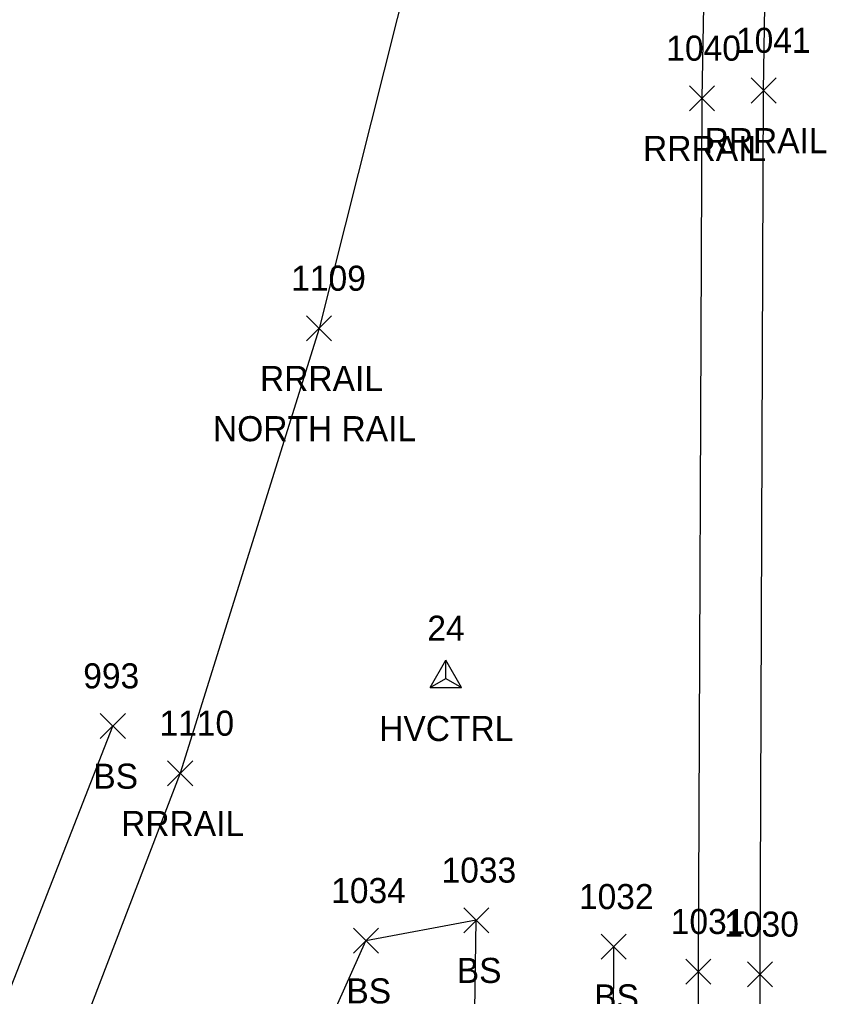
# Model space of a CAD drawing. Extents: x 1764889 to 1767296, y 695936 to 698960.
# Drawn here: x 1766353.9 to 1766418.2, y 696640.9 to 696718.8 of the extents above; entities that cross this region are included whole.
import ezdxf

# ---------------------------------------------------------------- set-up
doc = ezdxf.new("R2010")
doc.units = 0
for name, color, linetype in [('C_A', 7, 'Continuous'), ('C_I', 7, 'Continuous'), ('CPSM', 7, 'Continuous'), ('L_A', 7, 'Continuous'), ('L_I', 7, 'Continuous'), ('L_TIC', 7, 'Continuous'), ('LELB', 7, 'Continuous'), ('R_A', 7, 'Continuous'), ('R_C', 7, 'Continuous'), ('R_I', 7, 'Continuous'), ('R_TIC', 7, 'Continuous'), ('RR', 7, 'Continuous')]:
    doc.layers.add(name, color=color, linetype=linetype)

msp = doc.modelspace()

# ---------------------------------------------------------------- linework, layer by layer
at = {"layer": 'CPSM'}
for p, q in [((1766386.631, 696665.58), (1766387.881, 696667.745)), ((1766389.131, 696665.58), (1766387.881, 696667.745)), ((1766387.882, 696666.302), (1766387.881, 696667.745)), ((1766386.631, 696665.58), (1766387.882, 696666.302)), ((1766387.882, 696666.302), (1766387.882, 696666.302)), ((1766387.882, 696666.302), (1766389.131, 696665.58)), ((1766386.631, 696665.58), (1766389.131, 696665.58))]:
    msp.add_line(p, q, dxfattribs=at)
at = {"layer": 'L_TIC'}
for points in [[(1766360.339, 696661.502), (1766362.339, 696663.502)], [(1766362.339, 696661.502), (1766360.339, 696663.502)], [(1766389.323, 696646.013), (1766391.323, 696648.013)], [(1766391.323, 696646.013), (1766389.323, 696648.013)], [(1766380.522, 696644.378), (1766382.522, 696646.378)], [(1766382.522, 696644.378), (1766380.522, 696646.378)], [(1766380.522, 696644.378), (1766382.522, 696646.378)], [(1766382.522, 696644.378), (1766380.522, 696646.378)], [(1766400.28, 696643.9), (1766402.28, 696645.9)], [(1766402.28, 696643.9), (1766400.28, 696645.9)]]:
    msp.add_lwpolyline(points, dxfattribs=at)
at = {"layer": 'LELB'}
for points in [[(1766311.883, 696556.718), (1766333.813, 696592.111), (1766361.339, 696662.502)], [(1766365.103, 696608.671), (1766365.94, 696600.801), (1766371.66, 696593.655), (1766389.507, 696593.169), (1766390.323, 696647.013), (1766381.522, 696645.378)], [(1766341.436, 696578.464), (1766353.949, 696598.4), (1766365.103, 696608.671), (1766381.522, 696645.378)], [(1766376.43, 696369.053), (1766399.377, 696421.909), (1766400.574, 696461.932), (1766402.32, 696486.131), (1766401.07, 696549.523), (1766401.07, 696591.37), (1766401.28, 696644.9)]]:
    msp.add_lwpolyline(points, dxfattribs=at)
at = {"layer": 'R_TIC'}
for points in [[(1766407.329, 696711.561), (1766409.329, 696713.561)], [(1766409.329, 696711.561), (1766407.329, 696713.561)], [(1766412.234, 696712.185), (1766414.234, 696714.185)], [(1766414.234, 696712.185), (1766412.234, 696714.185)], [(1766376.778, 696693.214), (1766378.778, 696695.214)], [(1766378.778, 696693.214), (1766376.778, 696695.214)], [(1766365.704, 696657.729), (1766367.704, 696659.729)], [(1766367.704, 696657.729), (1766365.704, 696659.729)], [(1766407.033, 696641.916), (1766409.033, 696643.916)], [(1766409.033, 696641.916), (1766407.033, 696643.916)], [(1766411.953, 696641.704), (1766413.953, 696643.704)], [(1766413.953, 696641.704), (1766411.953, 696643.704)]]:
    msp.add_lwpolyline(points, dxfattribs=at)
at = {"layer": 'RR'}
for points in [[(1766414.51, 696927.612), (1766410.629, 696876.833), (1766407.503, 696845.702), (1766404.418, 696820.755), (1766396.985, 696776.652), (1766388.165, 696735.438), (1766377.778, 696694.214), (1766366.704, 696658.729), (1766355.141, 696628.572), (1766340.229, 696595.43), (1766321.371, 696561.379), (1766312.455, 696547.475), (1766299.858, 696528.94)], [(1766415.396, 696332.206), (1766414.474, 696421.49), (1766413.91, 696486.121), (1766413.465, 696550.63), (1766413.063, 696590.677), (1766412.953, 696642.704), (1766413.234, 696713.185), (1766413.819, 696750.286), (1766414.895, 696799.385)], [(1766410.405, 696332.082), (1766409.462, 696420.445), (1766408.849, 696485.765), (1766408.527, 696550.299), (1766408.18, 696590.823), (1766408.033, 696642.916), (1766408.329, 696712.561), (1766409.017, 696750.784), (1766409.913, 696798.981)]]:
    msp.add_lwpolyline(points, dxfattribs=at)

# ---------------------------------------------------------------- texts
at = {"layer": 'C_A'}
msp.add_text('HVCTRL', height=2, dxfattribs=at).set_placement((1766382.575, 696661.302))
at = {"layer": 'C_I'}
msp.add_text('24', height=2, dxfattribs=at).set_placement((1766386.417, 696669.302))
at = {"layer": 'L_A'}
for p in [(1766359.78, 696657.502), (1766388.764, 696642.013), (1766379.962, 696640.378), (1766379.962, 696640.378), (1766399.721, 696639.9)]:
    msp.add_text('BS', height=2, dxfattribs=at).set_placement(p)
at = {"layer": 'L_I'}
for s, p in [('993', (1766358.977, 696665.502)), ('1033', (1766387.552, 696650.013)), ('1034', (1766378.75, 696648.378)), ('1034', (1766378.75, 696648.378)), ('1032', (1766398.509, 696647.9))]:
    msp.add_text(s, height=2, dxfattribs=at).set_placement(p)
at = {"layer": 'R_A'}
for p in [(1766408.526, 696708.185), (1766403.62, 696707.561), (1766373.07, 696689.214), (1766361.996, 696653.729)]:
    msp.add_text('RRRAIL', height=2, dxfattribs=at).set_placement(p)
at = {"layer": 'R_C'}
msp.add_text('NORTH RAIL', height=2, dxfattribs=at).set_placement((1766369.322, 696685.214))
at = {"layer": 'R_I'}
for s, p in [('1040', (1766405.471, 696715.561)), ('1041', (1766411.03, 696716.185)), ('1109', (1766375.566, 696697.214)), ('1110', (1766365.059, 696661.729)), ('1031', (1766405.829, 696645.916)), ('1030', (1766410.095, 696645.704))]:
    msp.add_text(s, height=2, dxfattribs=at).set_placement(p)

doc.saveas('drawing.dxf')
